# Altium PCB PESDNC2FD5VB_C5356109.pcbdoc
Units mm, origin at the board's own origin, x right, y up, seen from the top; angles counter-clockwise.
Board outline 14.52 x 13.74 mm, 2 copper layers (Top Layer, Bottom Layer), stack 0 mm thick; 1 components, 0 nets, 2 pads, 0 vias.
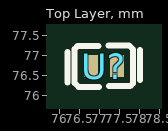
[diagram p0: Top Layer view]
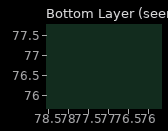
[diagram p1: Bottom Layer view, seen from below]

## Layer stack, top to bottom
Top Layer: signal copper (thickness not stored)
Bottom Layer: signal copper (thickness not stored)

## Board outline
84.37,69.85 69.85,69.85 69.85,83.59 84.37,83.59

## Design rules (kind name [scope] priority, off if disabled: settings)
PasteMaskExpansion "Paste Mask Expansion" [All] p1: expansion=0
SolderMaskExpansion "Solder Mask Expansion" [IsVia] p1: expansion=-25.4 istentingtop=TRUE
SolderMaskExpansion "Solder Mask Expansion" [All] p2: expansion=0.051 istentingtop=FALSE

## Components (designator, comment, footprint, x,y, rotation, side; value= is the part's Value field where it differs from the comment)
U? "PESDNC2FD5VB" X1-DFN1006-2_L1.0-W0.6-P0.65-BI 77.11,76.72 r0 top

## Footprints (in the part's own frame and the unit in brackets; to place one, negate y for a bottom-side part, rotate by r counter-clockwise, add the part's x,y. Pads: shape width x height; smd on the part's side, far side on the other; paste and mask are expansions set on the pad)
X1-DFN1006-2_L1.0-W0.6-P0.65-BI [mm]
  rect 0.35x0.55 smd: 1(-0.325,0) 2(0.325,0)
  silkscreen extent -0.91,-0.52 0.91,0.52

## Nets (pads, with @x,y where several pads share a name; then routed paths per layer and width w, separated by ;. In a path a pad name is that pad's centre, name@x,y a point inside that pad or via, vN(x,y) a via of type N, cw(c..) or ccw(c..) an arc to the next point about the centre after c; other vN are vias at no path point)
pads on no net: U?.1 U?.2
